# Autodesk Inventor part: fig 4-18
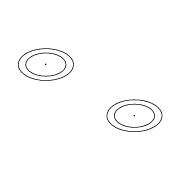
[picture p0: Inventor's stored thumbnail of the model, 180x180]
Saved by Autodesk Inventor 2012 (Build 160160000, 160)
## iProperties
Created: 2005-02
Part Number: fig 4-18
Document SubType Name: Modeling
Designer: CADCIM
Manufacturer: Standard
Standards Organization: Custom
Density: 1 g/cm^3
Material: Default
Author: CADCIM
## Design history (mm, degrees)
sketch "Sketch1"
  geometry: C1 r 7.935 at (-23.563, 7.599); C2 r 7.935 at (12.452, 7.599); C3 r 5.782 at (-23.563, 7.599); C4 r 5.782 at (12.452, 7.599)
  constraints: 4 centre point, 1 coincident, 1 equal radius, 1 other
